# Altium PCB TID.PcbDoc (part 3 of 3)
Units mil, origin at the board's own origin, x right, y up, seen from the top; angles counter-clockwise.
Board outline 3200 x 2650 mil, 4 copper layers (Top Layer, Mid-Layer 1, Mid-Layer 2, Bottom Layer), stack 61.2 mil thick; 193 components, 108 nets, 523 pads, 202 vias.
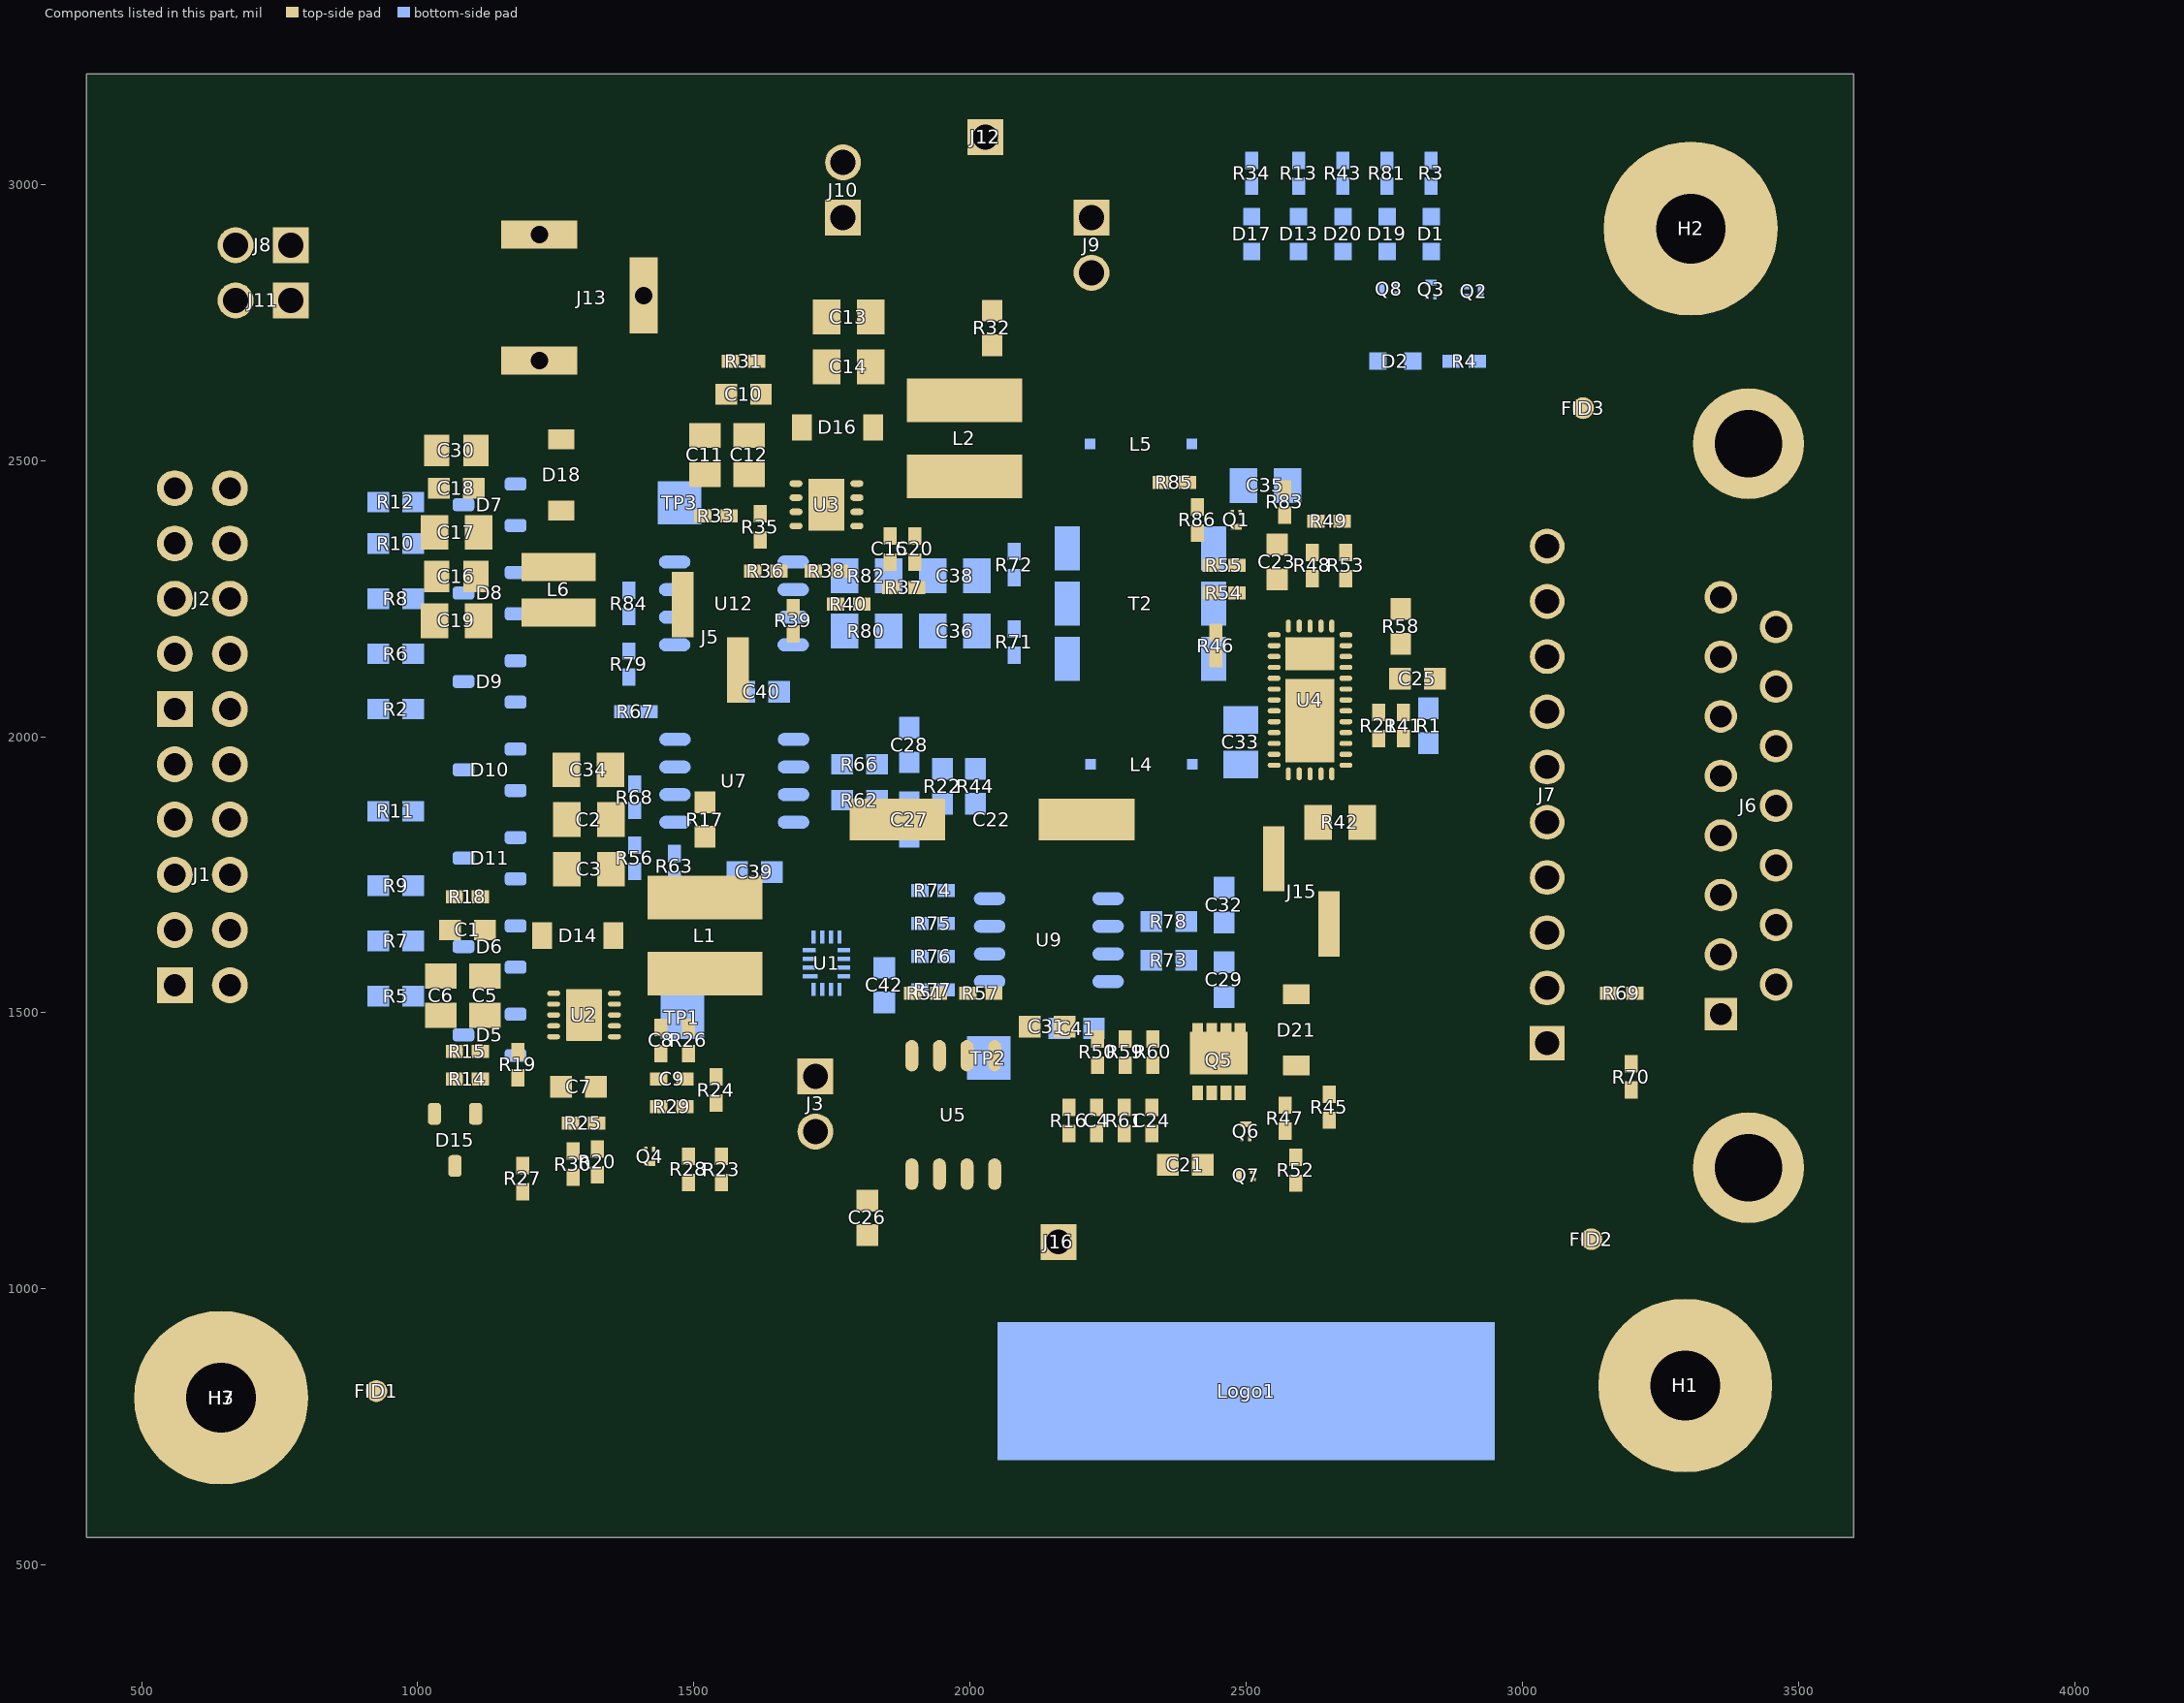
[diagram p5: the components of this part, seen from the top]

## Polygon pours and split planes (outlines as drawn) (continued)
GND on Bottom Layer "Top Layer-No Net 9" (solid, pour order 195): 450,3100 500,3150 625,3150 2950,3150 3000,3100 3000,3080 3000,3095 2945,3150 2995,3100 2995,1100 2945,1050 2850,1050 500,1050 450,1100
NetJ15_1 on Bottom Layer "Top Layer-No Net 9" (solid, pour order 181): 2570,2080 2570,1975 2585,1960 2645,1960 2660,1975 2660,2080 2645,2095 2585,2095
VOUT on Bottom Layer "Top Layer-No Net 9" (solid, pour order 186): 2275,2115 2275,2140 2295,2160 2340,2160 2350,2170 2380,2170 2410,2140 2410,2106.36 2403.64,2100 2290,2100
PWR_EN on Bottom Layer "Top Layer-No Net 9" (solid, pour order 185): 1093.2,1468.47 1088.63,1473.05 1087.01,1473.05 1057.37,1473.05 1047.34,1483.07 1013.12,1517.29 1013.12,1547.96 1010.17,1550.91 1009.73,1550.91 972.57,1550.91 969.62,1547.96 969.62,1472.46 1022.12,1419.95 1025.51,1416.56 1027.72,1416.56 1037.46,1416.56 1066.07,1445.17 1086.42,1445.17 1092.76,1451.51
NetC36_1 on Bottom Layer "Top Layer-No Net 9" (solid, pour order 189): 1958.04,2159.34 1827.74,2159.34 1826.7,2160.37 1826.7,2322.85 1827.77,2323.91 1957.33,2323.91 1958.48,2322.76 1958.13,2322.41 1958.13,2208.9
GND on Bottom Layer "Top Layer-No Net 9" (solid, pour order 192): 2995,2410 2995,2405 3010,2390 3080,2390 3095,2375 3095,2320 3075,2300 3010,2300 2990,2280 2990,2415
3.3V on Bottom Layer "Top Layer-No Net 9" (solid, pour order 103): 1119.4,2434.42 1251.55,2434.42 1265.07,2420.9 1232.23,2388.06 1139.43,2388.06
DSL2+ on Bottom Layer "Top Layer-No Net 9" (solid, pour order 102): 2525,2505 2540,2490 2540,2480 2540,2413.5 2543.5,2410 2560,2410 2665,2410 2540,2535 2525,2535
VOUT on Bottom Layer "Top Layer-No Net 9" (solid, pour order 106): 2690,1880 2670,1880 2665,1875 2665,1770 2670,1765 2695,1765
3.3V on Mid-Layer 1 "Top Layer-No Net 9" (solid, pour order 112): 1015,1305 990,1330 990,1375 1020,1405 1065,1405 1075,1405 1085,1395 1085,1355 1085,1345 1045,1305
VENCODER on Mid-Layer 1 "Top Layer-No Net 9" (solid, pour order 169): 2390,1265 2460,1265 2480,1285 2480,1850 2480,1900 2450,1930 2300,2080 2275,2080 2280,2080 2255,2105 2255,2120 2255,2145 2285,2175 2305,2175 2330,2200 2370,2240 2370,2265 2400,2295 2400,2355 2400,2365 2390,2375 2280,2375 2255,2350 2185,2280 2185,2230 2185,2070 2200,2055 2200,1615 2345,1470 2345,1375 2345,1285 2365,1265
VOUT on Mid-Layer 1 "Top Layer-No Net 9" (solid, pour order 148): 2330,2150 2375,2150 2390,2135 2390,2095 2355,2095
VOUT on Mid-Layer 1 "Top Layer-No Net 9" (solid, pour order 147): 2685,1880 2760,1880 2780,1860 2780,1830 2780,1825 2720,1765 2645,1765 2510,1900 2310,2100 2290,2100 2275,2115 2275,2140 2285,2150 2345,2150 2350,2145 2350,2135 2565,1920 2605,1880 2680,1880
VOUT on Mid-Layer 1 "Top Layer-No Net 9" (solid, pour order 161): 2285,2150 2290,2155 2330,2155 2300,2155 2302.07,2160 2340,2160 2350,2170 2365,2170 2380,2170 2405,2145 2410,2140 2410,2055 2371.36,2055 2320,2106.36
VOUT on Mid-Layer 1 "Top Layer-No Net 9" (solid, pour order 163): 2280,2145 2295,2160 2310,2160 2310,2150 2305,2145
NetJ15_1 on Mid-Layer 1 "Top Layer-No Net 9" (solid, pour order 179): 2615,2095 2585,2095 2570,2080 2570,1975 2585,1960 2645,1960 2660,1975 2660,2080 2645,2095
GND on Mid-Layer 1 "Top Layer-No Net 9" (solid, pour order 196): 450,3100 500,3150 2950,3150 2995,3105 2995,2405 3010,2390 3080,2390 3095,2375 3095,2320 3075,2300 3010,2300 2995,2285 2995,1100 2945,1050 2860,1050 500,1050 450,1100
3.3V on Mid-Layer 2 "Top Layer-No Net 9" (solid, pour order 111): 1015,1305 990,1330 990,1375 1020,1405 1065,1405 1075,1405 1085,1395 1085,1355 1085,1345 1045,1305
VOUT on Mid-Layer 2 "Top Layer-No Net 9" (solid, pour order 149): 2680,1870 2680,1880 2690,1880 2695,1880 2760,1880 2780,1860 2780,1825 2720,1765 2685,1765 2680,1770
VENCODER on Mid-Layer 2 "Top Layer-No Net 9" (solid, pour order 172): 2355,1370 2355,1275 2365,1265 2395,1265 2460,1265 2480,1285 2480,1330 2475,1335 2475,1370 2470,1375 2360,1375
GND on Mid-Layer 2 "Top Layer-No Net 9" (solid, pour order 108): 2985,2275 3010,2300 3075,2300 3095,2320 3095,2375 3080,2390 3010,2390 2985,2415
GND on Mid-Layer 2 "Top Layer-No Net 9" (solid, pour order 194): 2995,3105 2950,3150 2915,3150 500,3150 450,3100 450,1100 500,1050 2944.96,1050 2995,1100.04
NetJ15_1 on Mid-Layer 2 "Top Layer-No Net 9" (solid, pour order 180): 2570,2080 2570,1975 2585,1960 2645,1960 2660,1975 2660,2080 2645,2095 2585,2095
VENCODER on Mid-Layer 2 "Top Layer-No Net 9" (solid, pour order 182): 2385.23,2369.73 2276.26,2369.73 2240.86,2334.34 2240.86,2209.34 2245.86,2204.34 2320.86,2204.34 2390.86,2274.34 2391.16,2363.77
VOUT on Mid-Layer 2 "Top Layer-No Net 9" (solid, pour order 184): 2275,2115 2275,2140 2295,2160 2340,2160 2350,2170 2380,2170 2410,2140 2410,2106.36 2403.64,2100 2290,2100
VOUT on Mid-Layer 2 "Top Layer-No Net 9" (solid, pour order 109): 2685,1880 2680,1880 2675,1875 2675,1770 2680,1765 2690,1765 2690,1870

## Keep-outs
Keep-Out Layer:
  lines w10: 400,550 400,3200 3600,3200 3600,550 400,550 ; 4950,3455 cw(c4950,3450) 4955,3450 ccw(c4950,3450) 4950,3455
  text ".Layer_Name" at 577,-858.49 h60

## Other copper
Top Layer:
  pour cut-out: 1065.74,1186.66 1103.94,1148.45 1144.62,1148.45 1143.94,1149.13 1143.94,1159.24 1134.73,1168.45 1134.73,1184.63 1140.35,1190.25 1137.88,1192.72 1137.88,1199.91 1095.85,1199.91 1089.79,1193.85 1068.21,1193.85
  pour cut-out: 1542.84,2203.52 1542.84,2194.09 1549.76,2187.17 1550.07,2187.48 1590.33,2187.48 1599.97,2197.13 1592.53,2204.57 1592.53,2205.2 1546.51,2205.2 1546.2,2204.89
  pour cut-out: 1429.61,2254.23 1429.61,2320.64 1436.85,2327.88 1452.35,2312.38 1452.35,2310.57 1447.22,2305.44 1447.22,2246.48
  pour cut-out: 2685.85,1757.97 2685.42,1757.97 2672.59,1770.79 2665.96,1770.79 2661.39,1766.23 2661.39,1755.25 2656.93,1750.79 2656.93,1746.77 2662.26,1741.44 2677.05,1741.44
  pour cut-out: 1508.05,1429.89 1519.05,1429.89 1519.17,1429.77 1519.17,1424.39 1524.19,1419.37 1524.19,1409.8 1520.84,1406.45 1520.84,1317.71 1526.34,1312.21 1526.34,1251.22 1530.29,1247.27 1530.29,1216.3 1524.67,1210.67 1513.19,1210.67 1509.6,1214.26 1509.6,1259.11 1503.74,1264.97 1503.74,1311.85 1507.33,1315.44 1507.33,1347.01 1505.18,1349.16 1458,1349.16 1457.88,1349.28 1457.88,1358.77 1504.39,1358.77 1507.65,1362.02 1507.65,1427.65
  pour cut-out: 1729.77,2281.32 1748.06,2281.32 1750.82,2278.56 1750.82,2262.11 1749.51,2260.8 1749.24,2261.06 1729.9,2261.06
  pour cut-out: 1511.02,2260.95 1511.02,2247.61 1512.26,2246.37 1542.97,2246.37 1542.97,2260.36 1541.45,2261.89 1538.98,2259.41 1518.12,2259.41 1517.93,2259.61
  pour cut-out: 1585.78,2430.01 1586.71,2429.08 1586.71,2413.88 1600.98,2413.88 1602.53,2412.33 1603.46,2413.26 1603.46,2426.91
  pour cut-out: 1375.88,1717.94 1401.51,1717.94 1401.51,1686.06 1400.67,1685.23 1399.84,1686.06 1393.17,1686.06 1393.17,1692.52 1372.55,1713.15
  pour cut-out: 1391.72,1666.89 1391.92,1666.68 1404.84,1666.68 1404.84,1662.31 1408.38,1658.77 1632.65,1658.77 1640.16,1666.28 1640.16,1629.22 1635.58,1624.64 1401.75,1624.64 1390.42,1635.98 1390.42,1652.23
  pour cut-out: 1139.99,1442.65 1159.66,1442.65 1161.08,1444.07 1160.17,1444.98 1160.17,1457.27 1154.09,1457.27 1148.27,1451.44 1143.1,1451.44
  pour cut-out: 1088.37,1410.69 1099.37,1410.69 1099.76,1410.31 1099.24,1409.79 1099.24,1400.09 1089.15,1400.09 1088.89,1400.34
  pour cut-out: 1220.91,1443.79 1229.51,1443.79 1232.83,1440.47 1232.83,1426.04 1230.61,1423.83 1230.34,1424.1 1223.96,1424.1
  pour cut-out: 1460.23,1310.83 1460.23,1310.22 1457.24,1303 1464.78,1295.46 1464.78,1292.9 1467.35,1290.34 1467.35,1278.39 1438.46,1249.5 1438.46,1242.38 1439.88,1240.96 1469.34,1240.96 1470.05,1241.67 1470.05,1262.02 1472.04,1264.01 1475.88,1264.01 1475.88,1309.98
  pour cut-out: 1572.03,2660.96 1572.03,2646.93 1646.16,2646.93 1655.31,2637.77 1662.02,2637.77 1662.02,2647.54 1669.65,2655.16 1669.65,2657.91 1659.27,2668.28 1639.45,2668.28 1633.04,2661.87
  pour cut-out: 1779.7,2643.58 1779.7,2604.79 1784.65,2599.84 1843.67,2599.84 1858.43,2585.08 1867.53,2585.08 1867.53,2616.36 1860.11,2623.79 1797.99,2623.79
  pour cut-out: 2135.89,2483.86 2113.12,2483.86 2109.21,2487.78 2109.21,2512.39 2095.17,2526.42 1890.18,2526.42 1857.55,2559.06 1857.55,2570.96 1858.46,2571.87 1863.95,2571.87 1881.03,2554.79 2097.31,2554.79 2107.38,2564.86 2107.38,2599.33 2109.21,2601.16 2137.88,2601.16 2141.23,2597.8 2141.23,2547.47 2146.12,2542.59 2146.12,2533.44 2136.35,2523.68 2136.35,2510.86
  pour cut-out: 1091.87,1690.39 1091.87,1677.68 1095.21,1674.35 1096.67,1675.81 1148.96,1675.81 1157.5,1684.35 1157.5,1689.35 1149.8,1697.06 1134.79,1697.06 1130.63,1692.89
  pour cut-out: 2352.32,1423.8 2352.32,1390.24 2360.64,1381.92 2382.27,1381.92 2387.81,1387.47 2387.81,1397.73 2360.92,1424.63 2354.81,1424.63
  pour cut-out: 2288.81,1506.44 2288.81,1481.2 2298.52,1471.5 2309.06,1482.03 2309.06,1496.18 2298.52,1506.71
  pour cut-out: 2488.36,1308.98 2488.36,1333.08 2489.88,1334.61 2502.08,1334.61 2508.8,1341.32 2544.79,1341.32 2551.2,1334.91 2551.2,1309.9 2492.63,1309.9 2491.41,1308.68
  pour cut-out: 2514.28,1401.1 2514.28,1393.48 2520.38,1387.38 2526.18,1387.38 2556.99,1418.18 2556.99,1433.13 2614.03,1433.13 2631.72,1415.44 2635.38,1415.44 2638.74,1418.79 2638.74,1456.62 2636.6,1458.75 2570.11,1458.75 2565.22,1453.87
  pour cut-out: 2723.16,2050.25 2707.32,2066.09 2702.84,2066.09 2696.81,2060.06 2696.81,1943.49 2690.79,1937.46 2670.47,1937.46 2666.51,1933.5 2666.51,1909.57 2671.5,1904.58 2674.95,1904.58 2729.87,1959.5 2729.87,1971.9 2721.44,1980.34 2721.44,2046.46
  pour cut-out: 2772.25,2131.46 2772.25,2136.26 2777.17,2141.18 2778.11,2140.24 2808.68,2140.24 2808.68,2134.13 2807.84,2133.28
  pour cut-out: 2452.04,1255.89 2455.09,1258.94 2469.12,1258.94 2473.39,1254.67 2473.39,1191.52 2475.22,1189.69 2500.84,1189.69 2510.3,1180.24 2546.29,1180.24 2551.18,1175.36 2567.04,1175.36 2573.75,1168.65 2608.28,1168.65 2619.05,1157.88 2480.16,1157.88 2451.75,1186.29 2451.75,1252.59
  pour cut-out: 2254.37,1551.77 2233.46,1572.68 2225.28,1572.68 2217.79,1565.19 2217.79,1547.45 2248.02,1547.45 2249.13,1546.34
  pour cut-out: 2029.5,1382.17 2029.5,1513.34 2024.51,1518.33 1961.56,1518.33 1954.9,1511.67 1954.9,1452.61 1962.95,1444.56 1962.95,1398.81 1956.29,1392.15 1956.29,1361.65 1961,1356.93 1961,1354.58 1962.64,1352.94 1965.3,1355.6 1977.51,1355.6 1977.51,1449.68 1983.46,1455.62 2004.28,1455.62 2011.33,1448.58 2011.33,1389.1 2017.43,1382.99
  pour cut-out: 2403.44,2324.58 2397.07,2318.21 2397.07,2276.02 2403.09,2269.99 2407.57,2269.99 2416.52,2278.95 2468.53,2278.95 2470.25,2280.67 2470.25,2289.28 2467.66,2291.86 2414.46,2291.86 2412.56,2293.76 2412.56,2317.17 2405.5,2324.23
  pour cut-out: 2698.96,2285.41 2718.93,2265.44 2722.54,2265.44 2726.97,2269.88 2726.97,2381.64 2725.86,2381.64 2702.57,2404.93 2697.58,2399.94 2694.81,2399.94 2694.81,2373.87 2692.59,2371.66 2689.54,2371.66 2687.04,2369.16 2687.32,2368.88 2687.32,2357.23 2693.14,2357.23 2698.41,2351.97 2698.41,2287.63
  pour cut-out: 1064.8,2271.42 1064.8,2228.58 1075,2238.77 1075,2266.5
  pour cut-out: 2333.05,2207.57 2339.92,2200.69 2422.43,2200.69 2425.76,2204.02 2425.76,2208.61 2428.47,2211.32 2460.98,2211.32 2464.31,2207.98 2464.31,2201.32 2508.9,2201.32 2510.56,2199.65 2516.81,2205.9 2516.81,2207.36 2481.81,2242.36 2411.39,2242.36 2408.47,2239.44 2408.47,2235.49 2398.68,2225.69 2380.34,2225.69 2373.47,2232.57 2373.47,2234.44 2372.84,2234.44 2367.63,2239.65 2337.01,2209.03 2333.88,2209.03
  pour cut-out: 1032.4,1732.46 1032.91,1731.95 1072.55,1731.95 1072.55,1743.46 1071.02,1744.99 1071.02,1764.43 1078.68,1772.1 1084.82,1772.1 1084.82,1781.79 1089.81,1786.78 1074.12,1786.78 1032.23,1744.89 1032.23,1743.54
  pour cut-out: 2740.75,2389.98 2756,2374.73 2759.26,2374.73 2763.17,2378.64 2763.17,2400.67 2760.82,2403.01 2749.74,2403.01 2742.44,2395.71 2742.44,2394.28
  pour cut-out: 2712.37,2433.06 2708.81,2429.5 2708.81,2424.08 2714.8,2418.09 2723.38,2418.09 2727.83,2422.54 2727.83,2428.29 2722,2434.11
  pour cut-out: 1504.84,2301.73 1504.84,2289.41 1510.65,2283.6 1516.69,2283.6 1523.56,2290.48 1523.56,2298.41 1517.28,2304.69
  text ".Layer_Name" at 577,-858.49 h60
Mid-Layer 1:
  pour cut-out: 1413.32,1475.73 1413.58,1475.47 1425.61,1475.47 1547.35,1353.74 1542.43,1353.74 1532.47,1343.77 1415.13,1461.11 1415.13,1463.05
  pour cut-out: 1680.21,1274.63 1679.81,1274.63 1669.85,1264.67 1700.69,1233.82 1701.34,1233.82 1701.34,1235.67 1712.18,1246.51
  pour cut-out: 966.8,2000.19 966.8,1946.81 965.89,1945.89 966.19,1945.59 977.18,1945.59 977.18,1950.47 987.85,1961.14 993.04,1961.14 1007.99,1976.09 1007.99,1979.45 1001.88,1985.55 989.68,1985.55 975.96,1999.27
  pour cut-out: 1232.01,1402.44 1234.28,1400.17 1234.28,1327.57 1236.3,1325.55 1236.3,1313.2 1230.5,1307.4 1230.5,1296.56 1340.92,1296.56 1342.43,1295.05 1342.43,1305.13 1332.6,1314.96 1332.6,1322.78 1249.91,1405.47 1238.82,1405.47
  pour cut-out: 727.54,2853.45 727.54,2830.19 730.13,2827.61 731.6,2829.08 797.3,2829.08 797.3,2829.82 804.68,2837.21 792.87,2849.02 792.87,2853.08
  pour cut-out: 808.38,2747.88 832,2747.88 835.32,2751.21 831.63,2754.9 831.63,2811.37 830.52,2811.37 816.13,2825.76 808.38,2818.01
  pour cut-out: 1530.17,2166.1 1530.17,2149.77 1534.49,2145.45 1537.27,2148.24 1606.31,2148.24 1606.31,2157.54 1552.68,2211.18 1542.98,2211.18 1542.98,2194.05 1542.52,2193.58 1547.1,2189 1547.1,2178.58 1538.8,2170.28
  pour cut-out: 1046.1,1444.44 1044.47,1442.81 1044.47,1413.17 1076.55,1413.17 1075.33,1414.39 1075.33,1423.73 1073.3,1423.73 1050.56,1446.47
  pour cut-out: 969.36,1517.52 970.99,1515.89 970.99,1373.38 981.95,1373.38 982.76,1372.57 1019.3,1409.11 1019.3,1418.86 1013.62,1424.54 1013.62,1435.5 1024.58,1446.47 1038.79,1446.47 1044.07,1451.74 978.29,1517.52 978.29,1518.33
  pour cut-out: 1011.3,1300.8 1011.3,1300.23 1004.48,1293.41 1023.99,1273.9 1141.04,1273.9 1147.86,1280.72 1147.86,1284.51 1094.45,1337.92 1087.44,1337.92 1049.94,1300.42 1044.64,1300.42
  pour cut-out: 1731.88,2978.16 1802.63,2978.16 1804.04,2979.57 1804.04,2991.46 1800.91,2991.46 1788.08,3004.3 1787.76,3003.99 1751.29,3003.99 1751.29,3002.11 1733.6,2984.42
  pour cut-out: 879.57,2473.75 881.04,2475.22 881.04,2489.5 904.55,2513 988.09,2513 988.3,2512.79 988.3,2503.77 960.6,2476.06 951.99,2476.06 944.43,2468.5 944.43,2462.63 913.79,2431.98 910.85,2431.98 906.65,2436.18 906.65,2455.07 914.63,2463.05 919.88,2463.05 929.32,2472.49 928.9,2472.91 928.9,2489.71 922.18,2496.42 911.9,2496.42 898.46,2482.99 898.46,2480.89 890.28,2472.7
  pour cut-out: 1008.04,2444.36 1008.04,2441.98 1014.45,2435.58 1020.49,2441.62 1027.99,2441.62 1027.99,2448.57 1022.5,2454.06 1020.85,2452.41 1011.7,2452.41
  text "1.1" at 3305,1000 h60
Mid-Layer 2:
  pour cut-out: 1853.36,1615.19 1869.32,1615.19 1871.72,1617.59 1869.75,1619.57 1869.75,1635.67 1855.06,1635.67 1854.07,1634.68
Bottom Layer:
  pour cut-out: 2093.82,2264.32 2098.41,2259.72 2098.41,2233.63 2105.58,2240.79 2105.58,2244.32 2109.75,2248.49 2114.99,2248.49 2117.98,2251.49 2128.14,2251.49 2141.07,2238.55 2142.89,2240.37 2146.63,2240.37 2146.63,2282.06 2142.57,2286.13 2135.94,2286.13 2135.94,2280.57 2129.63,2274.26 2100.45,2274.26 2099.91,2274.79
  pour cut-out: 2099.4,2328.31 2099.27,2328.18 2099.27,2302.96 2100.04,2303.73 2129.41,2303.73 2138.98,2294.16 2141.31,2294.16 2146.49,2299.33 2146.49,2328.83 2146.23,2329.09
  pour cut-out: 2098.61,2152.89 2100.28,2154.55 2147.7,2154.55 2147.7,2229.43 2144.92,2232.2 2137.16,2232.2 2132.35,2227.39 2132.35,2223.87 2126.17,2217.7 2119.84,2217.7 2119.84,2215.5 2098.36,2194.03
  pour cut-out: 1637.57,1934.71 1637.57,1904.83 1639.31,1903.09 1645.67,1903.09 1655.5,1912.92 1705.44,1912.92 1711.03,1907.33 1744.58,1907.33 1744.58,1931.05 1743.04,1932.59 1709.88,1932.59 1703.13,1925.84 1658.01,1925.84 1647.02,1936.83 1639.88,1936.83
  pour cut-out: 1700.78,1869.18 1705.56,1873.96 1705.56,1879.43 1707.27,1881.13 1736.99,1881.13 1737.33,1880.79 1735.96,1879.43 1735.96,1855.51 1726.4,1855.51 1718.54,1863.37 1718.54,1864.4
  pour cut-out: 2430.64,2007.43 2434.11,2007.43 2446.45,1995.09 2452.43,2001.07 2452.43,2043.68 2439.32,2056.79 2429.87,2047.35 2429.87,2039.63
  pour cut-out: 2373.64,2180.45 2378.74,2175.36 2383.19,2175.36 2408.22,2150.33 2416.91,2159.03 2416.91,2226.9 2409.49,2234.32 2407.16,2234.32 2397.4,2224.56 2377.04,2224.56
  pour cut-out: 1937.3,1582.05 1937.59,1581.76 1937.59,1562.78 1957.73,1562.78 1959.61,1560.9 1967.44,1568.72 2005.97,1568.72 2011.91,1574.66 2053.78,1574.66 2053.78,1585.24 2048.42,1590.6 2045.95,1588.14 2015.68,1588.14 2010.17,1593.64 1982.36,1593.64 1978.16,1589.44 1978.16,1583.93
  pour cut-out: 1937.88,1643.76 2007.13,1643.76 2012.49,1638.4 2053.49,1638.4 2053.49,1625.95 2053.05,1625.51 2011.48,1625.51 2005.97,1620.01 1937.59,1620.01 1936.87,1620.73
  pour cut-out: 1934.61,1703.24 1934.61,1681.82 1937.37,1679.06 1976.82,1679.06 1976.82,1672.91 1980.64,1669.09 2003.97,1669.09 2008.85,1673.97 2051.69,1673.97 2053.26,1675.55 2053.26,1688.25 2009.47,1688.25 2003.25,1694.47 1967.84,1694.47 1960.95,1701.36
  pour cut-out: 2980.22,1627.5 2980.22,1626.05 2991.54,1614.72 3001.82,1625 3001.82,1627.24 2994.04,1635.01
  pour cut-out: 2802.06,1960.46 2794.45,1952.84 2869.55,1952.84 2869.94,1952.45 2870.44,1952.94 2870.44,1968.67
  pour cut-out: 2952.63,2227.67 2948.77,2223.81 2948.77,2217.64 2992.16,2174.26 3004.5,2186.6 3005.46,2186.6 3005.46,2218.99 2995.43,2229.02
  pour cut-out: 1727.42,1614.31 1727.42,1584.02 1730.77,1580.66 1736.4,1580.66 1747.89,1592.16 1751.36,1592.16 1752.68,1593.47 1752.68,1614.67 1748.97,1618.38 1748.25,1617.66 1730.53,1617.66
  pour cut-out: 919.36,2451.36 919.53,2451.18 939.16,2451.18 944.85,2456.87 944.85,2469.26 943.97,2470.13 938.05,2470.13 933.72,2474.46 932.52,2474.46 932.52,2474.26 919.54,2461.27 919.54,2460.9
  pour cut-out: 1065.67,2081.93 1104.49,2081.93 1107.27,2079.16 1107.27,1964.95 1104.24,1961.93 1096.17,1961.93 1093.4,1964.7 1093.4,2045.12 1062.64,2075.88
  pour cut-out: 1048.13,1411.5 1048.96,1412.32 1072.71,1412.32 1091.65,1431.26 1091.65,1435.14 1087.3,1439.49 1068.48,1439.49 1046.25,1417.26 1046.25,1414.44
  pour cut-out: 1479.68,1590.98 1479.68,1592.32 1377,1695 1359.12,1677.11 1350.27,1677.11 1350.27,1668.57 1350.25,1668.55 1427.55,1591.25 1434.21,1591.25
  pour cut-out: 1377.08,1826.08 1408.48,1826.08 1413.29,1821.27 1413.29,1817.14 1414.21,1816.23 1429.11,1816.23 1437.13,1808.2 1449.73,1808.2 1454.55,1813.02 1454.55,1822.87 1452.71,1824.71 1448.36,1824.71 1445.38,1827.69 1442.17,1827.69 1433,1836.85 1433,1858.85 1413.52,1858.85 1410.77,1856.1 1410.77,1847.17 1407.33,1843.73 1385.79,1843.73 1376.17,1834.1
  pour cut-out: 1439.88,1876.5 1434.38,1871 1434.38,1867.79 1441.48,1860.69 1444.07,1863.27 1491.13,1863.27 1491.13,1877.28 1490.53,1877.88
  pour cut-out: 1418.58,2026.26 1418.58,2020.94 1431.26,2008.26 1439.71,2008.26 1451.61,2020.16 1448.63,2023.13 1448.63,2028.3
  pour cut-out: 1440.48,1977.22 1440.48,1963.89 1442.84,1961.53 1445.83,1964.53 1488.95,1964.53 1488.95,1974.77 1487.86,1975.86
  pour cut-out: 1439.89,2297.84 1439.89,2285.73 1441.43,2284.19 1490.63,2284.19 1497.4,2277.43 1511,2277.43 1521.96,2288.39 1521.96,2297.93 1512.24,2307.65 1499.78,2307.65 1490.15,2298.02 1477.69,2298.02
  pour cut-out: 2462.78,2478.23 2462.78,2433.72 2433.99,2404.93 2433.99,2392.43 2428.12,2386.56 2418.84,2386.56 2418.84,2248.86 2414.29,2244.31 2409.18,2244.31 2396.68,2256.81 2382.66,2256.81 2375.84,2263.63 2376.03,2263.82 2376.03,2365.72 2329.06,2412.7 2334.55,2418.19 2334.55,2419.51 2417.89,2419.51 2418.08,2419.7 2420.16,2419.7 2432.66,2432.2 2432.66,2457.96 2455.01,2480.31 2457.48,2480.31
  pour cut-out: 2339.76,2644.48 2289.48,2644.48 2287.71,2642.71 2296.3,2634.12 2296.3,2441.42 2322.34,2415.37 2330.31,2415.37 2334.59,2419.65 2334.59,2468.83 2334.79,2469.02 2339.45,2469.02 2350.53,2480.1 2350.92,2480.1 2362.87,2492.06 2362.87,2494.88 2373.76,2505.76 2373.76,2551.93 2366.08,2559.61 2366.08,2563.21 2352.57,2576.72 2350.82,2576.72 2334.69,2592.85 2334.69,2639.6 2335.95,2640.87
  pour cut-out: 1654.53,2248.82 1654.53,2235.29 1656.26,2233.56 1658.03,2235.33 1705.4,2235.33 1711.04,2229.69 1800.69,2229.69 1804.41,2225.96 1804.41,2177.75 1811.3,2170.86 1817.56,2170.86 1820.85,2174.15 1820.85,2310.02 1814.74,2316.12 1804.1,2305.48 1804.1,2255.39 1801.44,2252.73 1709.24,2252.73 1705.33,2248.81 1693.12,2248.81
  pour cut-out: 2290.89,2092.94 2295.87,2087.96 2295.87,1830.4 2296.01,1830.54 2334.29,1830.54 2334.29,1887.74 2335.43,1888.88 2339.56,1888.88 2371.72,1921.04 2371.72,1928.16 2373.42,1929.86 2373.42,1962.16 2371.86,1963.73 2371.86,1977.96 2334.29,2015.53 2334.29,2053 2340.02,2058.73 2340.3,2058.45 2431.81,2058.45 2431.81,2095.05 2432.09,2095.33 2431.53,2095.88 2293.99,2095.88
  pour cut-out: 1924.8,1927.06 1924.8,1907.4 1925.22,1906.97 1745.47,1906.97 1741.84,1910.6 1741.84,1921.08 1746.32,1925.56 1924.58,1925.56
  pour cut-out: 2064.27,1889.02 2034.72,1889.02 2034.72,1893.83 2035.85,1894.96 2035.85,1915.35 2043.56,1915.35 2062.83,1896.4 2062.83,1895.12
  pour cut-out: 2480,1630 2470,1620 2435,1620 2435,1610 2430,1605 2420,1605 2420,1615 2415,1620 2280,1620 2275,1625 2225,1625 2225,1640 2275,1640 2280,1645 2300,1645 2305,1640 2415,1640 2420,1645 2420,1650 2435,1650 2435,1640 2440,1635 2475,1635
  pour cut-out: 2305,1570 2295,1560 2290,1560 2275,1575 2275,1590 2280,1595 2300,1595
  pour cut-out: 2521.64,1838.13 2568.88,1885.37 2661.33,1885.37 2661.33,1772.34 2657.01,1768.03 2645.58,1768.03 2582.34,1831.27 2527.23,1831.27 2524.43,1834.06
  pour cut-out: 2575.97,1949.79 2536.66,1949.79 2530.94,1955.51 2530.94,1977.08 2529.03,1977.08 2517.77,1988.33 2517.77,1997.68 2523.5,1997.68 2526.93,2001.12 2526.93,2059.32 2529.14,2061.52 2529.14,2064.95 2558.61,2064.95 2561.22,2067.56 2561.64,2067.13 2561.64,1972.62 2574.26,1960.01 2574.26,1958.65
  pour cut-out: 1858.23,1642.16 1858.23,1694.38 1808.51,1744.1 1800.64,1744.1 1795.64,1739.09 1795.64,1732.3 1839.27,1688.66 1839.27,1646.1 1845.35,1640.02 1855.37,1640.02
  pour cut-out: 1096.14,2280.48 1096.14,2322.27 1057.03,2361.39 1020.32,2361.39 1017.11,2364.61 1017.11,2370.77 1012.55,2375.32 1006.92,2375.32 997.82,2384.43 997.82,2397.83 1009.6,2397.83 1016.84,2405.06 1016.84,2411.76 1018.71,2413.64 1055.96,2413.64 1066.94,2402.65 1101.24,2402.65 1109.54,2394.35 1106.59,2391.4 1106.59,2279.4
  text ".Layer_Name" at 577,-858.49 h60

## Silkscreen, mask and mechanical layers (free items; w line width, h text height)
Top Overlay:
  text "GND" at 570,2510 h30 r90
  text "HIPER" at 718.61,2436.87 h30
  text "CLK" at 718.61,2336.2 h30
  text "TX" at 718.61,2236.54 h30
  text "DIR" at 718.61,2135.54 h30
  text "RX" at 718.61,2035.88 h30
  text "IMON" at 718.61,1950 h30
  text "SW_CTR" at 718.61,1840 h30
  text "HI_V" at 718.61,1735 h30
  text "PWR_EN" at 718.61,1635 h30
  text "FAULT" at 718.61,1540 h30
  text "GND" at 580,1410 h30 r90
  text ".Layer_Name" at 577,-858.49 h60
Bottom Overlay:
  lines w10: 450,2725 450,1100 500,1050 2070,1050 ; 450,2950 450,3100 500,3150 1000,3150 ; 1450,3150 2450,3150 ; 2250,1050 2945,1050 2995,1100 2995,1350 ; 2900,3150 2950,3150 2995,3105 2995,2450
  text "GND" at 2175,3040 h30
  text "PWR_EN" at 600,2870 h30
  text "HIPER" at 1669.71,2830 h30 r270
  text "HI_V" at 2120,2815 h30 r270
  text "SW_CTR" at 600,2775 h30
  text "GND" at 544.65,2522 h30 r270
  text "HIPER" at 856.31,2434.71 h30
  text "CLK" at 801.33,2329.71 h30
  text "GND" at 3192.07,2327.63 h30
  text "DSL4+" at 3252.06,2237.09 h30
  text "TX" at 771.34,2234.71 h30
  text "DIR" at 796.33,2134.71 h30
  text "DSL4-" at 3252.06,2128.28 h30
  text "RX" at 771.34,2034.71 h30
  text "DSL2+" at 3252.06,2030.02 h30
  text "IMON" at 826.32,1934.34 h30
  text "DSL2-" at 3252.06,1931.77 h30
  text "SW_CTR" at 891.3,1836.24 h30
  text "DATA+" at 3252.06,1830.26 h30
  text "HI_V" at 826.32,1735.71 h30
  text "DATA-" at 3252.06,1731.6 h30
  text "PWR_EN" at 891.3,1635.19 h30
  text "CLK+" at 3222.07,1632.13 h30
  text "FAULT" at 861.31,1535.62 h30
  text "CLK-" at 3222.07,1530.22 h30
  text "VENC" at 3222.07,1433.55 h30
  text "GND" at 548.36,1382.76 h30 r270
  text "GND" at 2087.07,1067.63 h30
  text "TI" at 1435,835 h60
  text ".CopyrightYear" at 1711,835 h60
  text "©" at 1810,830 h105
  text "Rev.E1" at 1210,710 h60
  text "TIDA-00179" at 1810,710 h60
  text ".Layer_Name" at 577,-858.49 h60
Top Paste:
  text ".Layer_Name" at 577,-858.49 h60
Bottom Paste:
  text ".Layer_Name" at 577,-858.49 h60
Top Solder:
  text ".Layer_Name" at 577,-858.49 h60
  text ".Layer_Name" at 577,-858.49 h60
Bottom Solder:
  text ".Layer_Name" at 577,-858.49 h60
Drill Guide:
  text ".Layer_Name" at 577,-858.49 h60
M1 Board Outline:
  the board outline again, w10
  text ".Layer_Name" at 577,-858.49 h60
M2 Board Dimensions:
  rectangle: 0,-275 125,-150
  rectangle: 125,-400 500,-275
  lines w7: 0,-275 1000,-275 ; 125,-400 125,-150 ; 250,-400 250,-150 ; 500,-400 500,-150 ; 750,-400 750,-150 ; 0,-400 1000,-400 1000,-150 0,-150 0,-400
  text ".Layer_Name" at 577,-858.49 h60
M3 3D STEP Top:
  text ".Layer_Name" at 577,-858.49 h60
M4 3D STEP Bottom:
  text ".Layer_Name" at 577,-858.49 h60
M5 Assembly Top:
  lines w10: -292,-930.17 6308,-930.17 ; -292,-726.83 6310,-726.83 ; -292,-523.5 -292,-1133.5 3713,-1133.5 6310,-1133.5 6310,-523.5 -291.5,-523.5 -291.5,-1133.5 1284,-1133.5 ; 2173,-1133.5 2173,-523.5 ; 3440,-726.83 3440,-523.5 ; 4280,-726.83 4280,-523.5 ; 4902,-1140 4902,-937.17
  text "COMPONENTS MARKED 'DNP' SHOULD NOT BE POPULATED." at 1153.5,-318.5 h60
  text "ASSEMBLY VARIANT:" at 1153,-434 h60
  text ".VariantName" at 2189,-434 h60
  text "PCB VIEWED FROM TOP SIDE" at -228.5,-655.67 h60
  text "BOARD #:" at 2248,-655.67 h60
  text ".PRJ_Number" at 2793.5,-655.67 h60
  text "REV:" at 3638,-655.67 h60
  text ".PCB_Rev" at 3929.5,-655.67 h60
  text "SVN REV:" at 4476,-655.67 h60
  text ".VersionControl_RevNumber" at 4982,-655.67 h60
  text "PLOT NAME =" at -228.5,-1064.34 h60
  text ".plot_File_Name" at 577,-1064.34 h60
  text "GENERATED    :" at 2250,-1064.34 h60
  text ".Print_Date" at 3119.5,-1064.34 h60
  text ".Print_Time" at 3848.5,-1064.34 h60
  text "TEXAS INSTRUMENTS" at 5113,-1064.34 h60
M6 Assembly Bottom:
  lines w10: -292.5,-727.33 6309.5,-727.33 ; -290.5,-930.67 6309.5,-930.67 ; 1115.5,-1140.5 1115.5,-937.67 ; 1737.5,-727.33 1737.5,-524 ; 2577.5,-727.33 2577.5,-524 ; 3844.5,-1134 3844.5,-524 ; 4733.5,-1134 6309,-1134 6309,-524 -292.5,-524 -292.5,-1134 2304.5,-1134 6309.5,-1134 6309.5,-524
  text "COMPONENTS MARKED 'DNP' SHOULD NOT BE POPULATED." at 6102,-318 h60
  text ".VariantName" at 5058,-434 h60
  text "ASSEMBLY VARIANT:" at 6097,-434 h60
  text ".VersionControl_RevNumber" at 1035.5,-656.17 h60
  text "SVN REV:" at 1541.5,-656.17 h60
  text ".PCB_Rev" at 2088,-656.17 h60
  text "REV:" at 2379.5,-656.17 h60
  text ".PRJ_Number" at 3224,-656.17 h60
  text "BOARD #:" at 3769.5,-656.17 h60
  text "PCB VIEWED FROM BOTTOM SIDE" at 6246,-656.17 h60
  text "TEXAS INSTRUMENTS" at 904.5,-1064.84 h60
  text ".Print_Time" at 2169,-1064.84 h60
  text ".Print_Date" at 2898,-1064.84 h60
  text "GENERATED    :" at 3767.5,-1064.84 h60
  text ".plot_File_Name" at 5440.5,-1064.84 h60
  text "PLOT NAME =" at 6246,-1064.84 h60
M9 Title Sheet:
  drawing of 57 lines, arcs and shapes, not listed
  text "1" at 739.84,8036.5 h70
  text "2" at 3235.5,8036.5 h70
  text "3" at 5724.84,8036.5 h70
  text "4" at 8231.51,8036.5 h70
  text "5" at 10730.5,8036.5 h70
  text "6" at 13235.5,8036.5 h70
  text "A" at -416.5,6893.5 h70
  text "A" at 14383.5,6893.5 h70
  text "B" at -416.5,4513.5 h70
  text "B" at 14383.5,4513.5 h70
  text "C" at -416.5,2138.5 h70
  text "C" at 14383.5,2138.5 h70
  text "PROJECT TITLE:" at 11343.5,277.5 h45
  text ".PRJ_Title" at 11393.5,144.17 h70
  text "DESIGNED FOR:" at 11343.5,-23.5 h45
  text ".PRJ_Customer" at 11393.5,-163.5 h70
  text "D" at -416.5,-231.5 h70
  text "D" at 14383.5,-231.5 h70
  text "FILE NAME:" at 11343.5,-323.5 h45
  text ".PCB_File_Name_No_Path" at 11393.5,-443.5 h70
  text "Texas Instruments (TI) and/or its licensors do not warrant the accuracy or completeness of this specification" at 6374,-605.34 h45
  text "ENGINEER:" at 11343.5,-613.5 h45
  text "LAYOUT BY:" at 12848.5,-613.5 h45
  text "or any information contained therein. TI and/or its licensors do not warrant that this design will meet" at 6329.01,-718 h45
  text ".PRJ_Engineer" at 11393.5,-768.49 h70
  text ".PCB_Layout" at 12899,-768.49 h70
  text "the specifications, will be suitable for your application or fit for any particular purpose, or will operate in" at 6329.01,-830.67 h45
  text ".Layer_Name" at 577,-858.49 h60
  text "ALTIUM DESIGNER VERSION:" at 12848.5,-923.5 h45
  text "an implementation. TI and/or its licensors do not warrant that the design is production worthy. You should" at 6329.01,-943.33 h45
  text "completely validate and test your design implementation to confirm the system functionality for your application." at 6374,-1056 h45
  text ".print_Scale" at 11393.5,-1056.83 h70
  text ".Application_BuildNumber" at 12899,-1056.83 h70
  text "1" at 739.84,-1263.5 h70
  text "2" at 3235.5,-1263.5 h70
  text "3" at 5724.84,-1263.5 h70
  text "4" at 8231.51,-1263.5 h70
  text "5" at 10730.5,-1263.5 h70
  text "6" at 13235.5,-1263.5 h70
M10 Fab Notes:
  drawing of 185 lines, arcs and shapes, not listed
  text "DESIGN INFORMATION" at 12381.02,5910 h60
  text "MIN. TRACK WIDTH:" at 11736.46,5730 h60
  text "8" at 12832.7,5730 h60
  text "MIL" at 12987.46,5730 h60
  text "MIN. CLEARANCE:" at 11736.46,5598 h60
  text "0.2" at 12772.7,5598 h60
  text "mm" at 12987.46,5598 h60
  text "MIN. VIA PAD SIZE:" at 11736.46,5466 h60
  text "24" at 12802.71,5466 h60
  text "MIL" at 12987.46,5466 h60
  text "0.05mm (2MIL)" at 12431.46,5324.29 h60
  text "MINIMUM ANNULAR RING" at 11407.23,5320 h60
  text "EXTERNAL" at 13139.46,5320 h60
  text "PER" at 11607.23,5202 h60
  text "IPC-D-275 CLASS 2 LEVEL C" at 11827.23,5202 h60
  text "MIL, HOLES" at 13315.46,5089.71 h60
  text "+/-" at 12923,5089 h60
  text "+/-" at 13777,5089 h60
  text "REGISTRATION TOLERANCES:" at 11407.23,5084 h60
  text "METAL" at 12607,5084 h60
  text "5" at 13183.2,5084 h60
  text "3" at 14016.2,5084 h60
  text "MIL" at 14132.46,5084 h60
  text "MATERIAL:" at 11332.46,4874.54 h60
  text "FR-4 High Tg" at 12318.9,4734.21 h60
  text "FR-408" at 11753.46,4725.64 h60
  text "X" at 12165.46,4725.64 h60
  text "OTHER" at 13241.46,4725.64 h60
  text "62 MIL (1.6mm) +/-10%" at 12073.56,4562.92 h60
  text "THICKNESS:" at 11407.23,4558.64 h60
  text "X" at 11945.4,4558.64 h60
  text "OTHER" at 13358.46,4558.64 h60
  text "TOLERANCE:" at 11407.23,4400.64 h60
  text "X" at 12246.53,4400.64 h60
  text "ANSI IPC-6012 TYPE 3 CLASS 2" at 12433.48,4400.64 h60
  text "OTHER +/-" at 12433.46,4244.64 h60
  text "BOW & TWIST:" at 11407.23,4087.64 h60
  text "X" at 12246.53,4087.64 h60
  text "ANSI IPC-6012 TYPE 3 CLASS 2" at 12433.48,4087.64 h60
  text "OTHER +/-" at 12433.46,3929.13 h60
  text "DRILLING:" at 11332.46,3790.64 h60
  text "REFERENCE:" at 11407.23,3673.64 h60
  text "X" at 12055.46,3673.64 h60
  text "AS SHOWN" at 12242.46,3673.64 h60
  text "X" at 12956.46,3673.64 h60
  text "NC_DRILL FILES" at 13093.46,3673.64 h60
  text "PTH MIN COPPER THICKNESS:" at 11407.23,3515.64 h60
  text "X" at 12757.46,3515.64 h60
  text "1MIL" at 12894.46,3515.64 h60
  text "OTHER" at 13391.46,3515.64 h60
  text "BOARD FINISH:" at 11332.46,3356.64 h60
  text "SILKSCREEN:" at 11487.68,3238.64 h60
  text "X" at 12436.46,3238.64 h60
  text "TOP" at 12562.46,3238.64 h60
  text "X" at 12946.46,3238.64 h60
  text "BOTTOM" at 13073.46,3238.64 h60
  text "SILKSCREEN COLOR:" at 11487.68,3071.64 h60
  text "X" at 12435.42,3071.64 h60
  text "WHITE" at 12562.46,3071.64 h60
  text "OTHER" at 13073.46,3071.64 h60
  text "SOLDER RESIST COLOR:" at 11487.68,2901.64 h60
  text "X" at 12055.42,2742.44 h60
  text "GREEN" at 12182.46,2742.44 h60
  text "BLUE" at 12773.46,2742.44 h60
  text "OTHER" at 13311.46,2742.44 h60
  text "IMMERSION GOLD (ENIG)" at 12393.46,2553.92 h60
  text "ENEPIG" at 13731,2550.64 h60
  text "SURFACE FINISH:" at 11332.46,2549.64 h60
  text "X" at 12206.51,2549.64 h60
  text "IMM. TIN/SILVER OR EQUIV" at 11662,2392.64 h60
  text "OTHER" at 13093.46,2392.64 h60
  text "ARRAY/PANEL:" at 11332.46,2213.64 h60
  text "CUT AND TRIM PER MECH LAYER 1" at 12393.46,2209.35 h60
  text "N.C. ROUTE" at 12393.46,2057.64 h60
  text "X" at 13072.46,2057.64 h60
  text "V. SCORE" at 13259.46,2057.64 h60
  text "CERTIFICATION:" at 11332.46,1920.64 h60
  text "MATERIALS AND WORKMANSHIP FOR ALL PCBS" at 12057.46,1920.64 h60
  text "TO MEET OR EXCEED THE REQUIREMENTS OF:" at 12057.46,1822.64 h60
  text "X" at 11683.96,1686.13 h60
  text "ANSI IPC-A-600F CLASS ->" at 11822.96,1686.13 h60
  text "X" at 13462.02,1686.13 h60
  text "2" at 13580.96,1686.14 h60
  text "1" at 13265.96,1684.64 h60
  text "3" at 13934.96,1684.64 h60
  text "X" at 11686.02,1526.64 h60
  text "UL 94V-0" at 11822.96,1526.64 h60
  text "X" at 12498.02,1526.64 h60
  text "RoHS" at 12634.96,1526.64 h60
  text "OTHER" at 13279.36,1526.64 h60
  text "PER ORDER" at 13676.42,1526.64 h60
  text "ADDITIONAL REQUIREMENTS:" at 11332.46,1385.64 h60
  text "MICROSECTION:" at 11407.23,1270.64 h60
  text "YES" at 12312.96,1270.64 h60
  text "REQUIRED" at 13174.46,1114.49 h60
  text "BARE BOARD ELEC. TEST:" at 11407.23,1111.64 h60
  text "NONE" at 12712.96,1111.64 h60
  text "X" at 13047.46,1111.64 h60
  text "PER ORDER" at 13766.46,1111.64 h60
  text "MANUFACTURER'S UL:" at 11407.23,954.64 h60
  text "RAIL" at 12572.96,950.35 h60
  text "METAL" at 13064.77,950.35 h60
  text "X" at 13440,950 h60
  text "SILK" at 13576.46,950.35 h60
  text ".Layer_Name" at 577,-858.49 h60
M11 Gerber Information:
  lines w10: -292,-930.17 6308,-930.17 ; -292,-726.83 6310,-726.83 ; -292,-523.5 -292,-1133.5 3713,-1133.5 6310,-1133.5 6310,-523.5 -291.5,-523.5 -291.5,-1133.5 1284,-1133.5 ; 2173,-1133.5 2173,-523.5 ; 3440,-726.83 3440,-523.5 ; 4280,-726.83 4280,-523.5 ; 4902,-1140 4902,-937.17
  text "ALL ARTWORK VIEWED FROM TOP SIDE" at -228.5,-655.67 h60
  text "BOARD #:" at 2248,-655.67 h60
  text ".PRJ_Number" at 2793.5,-655.67 h60
  text "REV:" at 3638,-655.67 h60
  text ".PCB_Rev" at 3929.5,-655.67 h60
  text "SVN REV:" at 4476,-655.67 h60
  text ".VersionControl_RevNumber" at 4982,-655.67 h60
  text "LAYER NAME =" at -228.5,-858.49 h60
  text "PLOT NAME =" at -228.5,-1064.34 h60
  text ".plot_File_Name" at 577,-1064.34 h60
  text "GENERATED    :" at 2250,-1064.34 h60
  text ".Print_Date" at 3119.5,-1064.34 h60
  text ".Print_Time" at 3848.5,-1064.34 h60
  text "TEXAS INSTRUMENTS" at 5113,-1064.34 h60
M12 Stackup:
  drawing of 191 lines, arcs and shapes, not listed
  text "Layer" at 9790.58,7830 h60
  text "Name" at 10200.49,7830 h60
  text "Material" at 11130.23,7830 h60
  text "Thickness" at 11990,7830 h60
  text "Constant" at 12639.84,7830 h60
  text "Board Layer Stack" at 13209.7,7830 h60
  text "1" at 9790.58,7710 h60
  text "Top Overlay" at 10200.49,7710 h60
  text "2" at 9790.58,7590 h60
  text "Top Solder" at 10200.49,7590 h60
  text "Solder Resist" at 11130.23,7590 h60
  text "0.40mil" at 11990,7590 h60
  text "3.5" at 12639.84,7590 h60
  text "3" at 9790.58,7470 h60
  text "Top Layer" at 10200.49,7470 h60
  text "Copper" at 11130.23,7470 h60
  text "1.40mil" at 11990,7470 h60
  text "4" at 9790.58,7350 h60
  text "Dielectric1" at 10200.49,7350 h60
  text "FR-4" at 11130.23,7350 h60
  text "59.20mil" at 11990,7350 h60
  text "4.8" at 12639.84,7350 h60
  text "5" at 9790.58,7230 h60
  text "Bottom Layer" at 10200.49,7230 h60
  text "Copper" at 11130.23,7230 h60
  text "1.40mil" at 11990,7230 h60
  text "6" at 9790.58,7110 h60
  text "Bottom Solder" at 10200.49,7110 h60
  text "Solder Resist" at 11130.23,7110 h60
  text "0.40mil" at 11990,7110 h60
  text "3.5" at 12639.84,7110 h60
  text "7" at 9790.58,6990 h60
  text "Bottom Overlay" at 10200.49,6990 h60
  text ".Layer_Name" at 577,-858.49 h60
M13 Component Bodies Top:
  text ".Layer_Name" at 577,-858.49 h60
M14 Component Bodies Bottom:
  text ".Layer_Name" at 577,-858.49 h60
M15 Courtyards Top:
  text ".Layer_Name" at 577,-858.49 h60
M16 Courtyards Bottom:
  text ".Layer_Name" at 577,-858.49 h60
Drill Drawing:
  circle w3.33: c5557.9,2885.05 r20.77
  circle w3.33: c5557.9,2635.8 r12.46
  circle w3.33: c5557.9,2635.8 r20.77
  lines w3.33: 5537.13,2251.55 5547.51,2251.55 5557.9,2241.16 5568.28,2251.55 5578.67,2251.55 5568.28,2261.93 5578.67,2272.32 5568.28,2272.32 5557.9,2282.7 5547.51,2272.32 5537.13,2272.32 5547.51,2261.93 5537.13,2251.55 ; 5537.13,2365.79 5578.67,2365.79 5578.67,2407.33 5537.13,2407.33 5537.13,2365.79 ; 5537.13,2511.18 5557.9,2490.41 5578.67,2511.18 5557.9,2531.95 5537.13,2511.18 ; 5537.13,2781.19 5578.67,2781.19 5557.9,2739.65 5537.13,2781.19 ; 5537.13,2988.9 5537.13,2999.28 5547.51,3009.67 5537.13,3020.05 5537.13,3030.44 5547.51,3030.44 5557.9,3020.05 5568.28,3030.44 5578.67,3030.44 5578.67,3020.05 5568.28,3009.67 5578.67,2999.28 5578.67,2988.9 5568.28,2988.9 5557.9,2999.28 5547.51,2988.9 5537.13,2988.9 ; 5537.13,3113.52 5578.67,3113.52 5578.67,3155.06 5537.13,3155.06 5537.13,3113.52 ; 5537.13,3279.68 5578.67,3279.68 5557.9,3238.14 5537.13,3279.68 ; 5545.44,2255.7 5551.67,2255.7 5557.9,2249.47 5564.13,2255.7 5570.36,2255.7 5564.13,2261.93 5570.36,2268.16 5564.13,2268.16 5557.9,2274.4 5551.67,2268.16 5545.44,2268.16 5551.67,2261.93 5545.44,2255.7 ; 5545.44,2772.88 5570.36,2772.88 5557.9,2747.96 5545.44,2772.88 ; 5545.44,3121.83 5570.36,3121.83 5570.36,3146.75 5545.44,3146.75 5545.44,3121.83
  lines w12: 5480,2203.78 7509.11,2203.78 ; 5480,3325.38 7509.11,3325.38 ; 5828.13,2079.15 5828.13,3450 ; 6170.32,2079.15 6170.32,3450 ; 6817.06,2079.15 6817.06,3450 ; 7086.38,2079.15 7086.38,3450 ; 5480,2079.15 7509.11,2079.15 7509.11,3450 5480,3450 5480,2079.15
  text "Symbol" at 5554.77,3362.76 h72
  text "Quantity" at 5865.52,3362.76 h72
  text "Finished Hole Size" at 6207.7,3362.76 h72
  text "Plated" at 6854.45,3362.76 h72
  text "Hole Type" at 7123.77,3362.76 h72
  text "2" at 5865.52,3238.14 h60
  text "7.87mil (0.200mm)" at 6207.7,3238.14 h60
  text "PTH" at 6854.45,3238.14 h60
  text "Round" at 7123.77,3238.14 h60
  text "200" at 5865.52,3113.52 h60
  text "8.00mil (0.203mm)" at 6207.7,3113.52 h60
  text "PTH" at 6854.45,3113.52 h60
  text "Round" at 7123.77,3113.52 h60
  text "15" at 5865.52,2988.9 h60
  text "39.37mil (1.000mm)" at 6207.7,2988.9 h60
  text "PTH" at 6854.45,2988.9 h60
  text "Round" at 7123.77,2988.9 h60
  text "20" at 5865.52,2864.27 h60
  text "40.00mil (1.016mm)" at 6207.7,2864.27 h60
  text "PTH" at 6854.45,2864.27 h60
  text "Round" at 7123.77,2864.27 h60
  text "10" at 5865.52,2739.65 h60
  text "43.31mil (1.100mm)" at 6207.7,2739.65 h60
  text "PTH" at 6854.45,2739.65 h60
  text "Round" at 7123.77,2739.65 h60
  text "12" at 5865.52,2615.03 h60
  text "45.28mil (1.150mm)" at 6207.7,2615.03 h60
  text "PTH" at 6854.45,2615.03 h60
  text "Round" at 7123.77,2615.03 h60
  text "2" at 5865.52,2490.41 h60
  text "122.05mil (3.100mm)" at 6207.7,2490.41 h60
  text "PTH" at 6854.45,2490.41 h60
  text "Round" at 7123.77,2490.41 h60
  text "3" at 5865.52,2365.79 h60
  text "125.98mil (3.200mm)" at 6207.7,2365.79 h60
  text "PTH" at 6854.45,2365.79 h60
  text "Round" at 7123.77,2365.79 h60
  text "3" at 5865.52,2241.16 h60
  text "31.50mil (0.800mm)" at 6207.7,2241.16 h60
  text "PTH" at 6854.45,2241.16 h60
  text "Slot" at 7123.77,2241.16 h60
  text "267 Total" at 5865.52,2116.54 h60
  text ".Layer_Name" at 577,-858.49 h60

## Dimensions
0,-400 to 1000,-400 on M2 Board Dimensions
400,550 to 400,3200 on M2 Board Dimensions
400,550 to 3600,550 on M2 Board Dimensions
